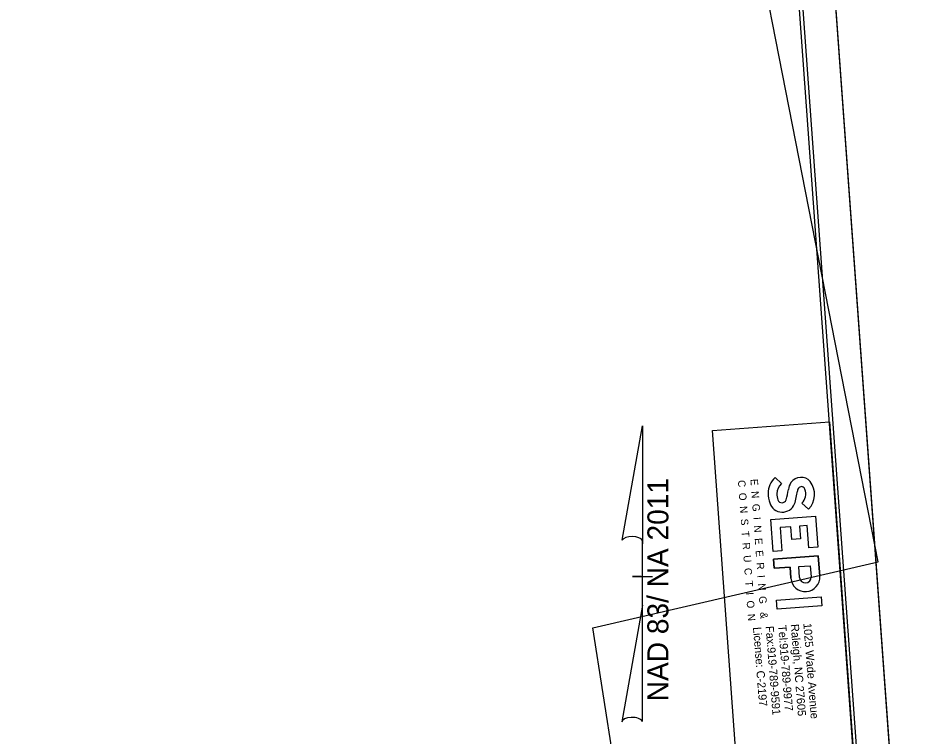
# Model space of a CAD drawing. Extents: x 2130580 to 2131806, y 642587 to 644485.
# Drawn here: x 2131193 to 2131806, y 643045 to 643536 of the extents above; entities that cross this region are included whole.
import ezdxf

# ---------------------------------------------------------------- set-up
doc = ezdxf.new("R2010")
doc.units = 0
for name, color, linetype in [('Old_Level_2', 7, 'Continuous'), ('Old_Level_58', 7, 'Continuous'), ('Old_Level_61', 7, 'Continuous'), ('Prop North Arrow NAD83 for Plan Sheets CELL', 7, 'Continuous'), ('Scratch_Level_1', 7, 'Continuous'), ('Sheet Border Standard 30in CELL', 7, 'Continuous'), ('Sheet Cutting Line CELL', 7, 'Continuous'), ('Sheet Plot Border Inside CELL', 7, 'Continuous'), ('Sheet Plot Border Outside CELL', 7, 'Continuous')]:
    doc.layers.add(name, color=color, linetype=linetype)

msp = doc.modelspace()

# ---------------------------------------------------------------- linework, layer by layer
at = {"layer": 'Old_Level_58'}
msp.add_lwpolyline([(2131747.69, 643259.81), (2131765.03, 643020.38), (2131685.21, 643014.6), (2131667.87, 643254.03)], close=True, dxfattribs=at)
at = {"layer": 'Old_Level_61'}
for p, q in [((2131710.59, 643221.85), (2131714.87, 643217.7)), ((2131733.51, 643200.1), (2131728.9, 643204.2)), ((2131707.6, 643193.22), (2131738.18, 643195.44)), ((2131738.18, 643195.44), (2131739.72, 643174.21)), ((2131709.19, 643171.3), (2131707.6, 643193.22)), ((2131721.42, 643188.1), (2131714, 643187.56)), ((2131714, 643187.56), (2131715.15, 643171.73)), ((2131722.06, 643179.35), (2131721.42, 643188.1)), ((2131732.64, 643188.91), (2131727.36, 643188.53)), ((2131727.36, 643188.53), (2131728, 643179.78)), ((2131733.74, 643173.78), (2131732.64, 643188.91)), ((2131728, 643179.78), (2131722.06, 643179.35)), ((2131715.15, 643171.73), (2131709.19, 643171.3)), ((2131739.72, 643174.21), (2131733.74, 643173.78)), ((2131741.16, 643154.37), (2131740.15, 643168.19)), ((2131727.35, 643153.37), (2131726.8, 643160.95)), ((2131711.62, 643137.91), (2131742.19, 643140.13)), ((2131742.19, 643140.13), (2131742.64, 643134.01)), ((2131712.06, 643131.79), (2131711.62, 643137.91)), ((2131742.64, 643134.01), (2131712.06, 643131.79))]:
    msp.add_line(p, q, dxfattribs=at)
for points in [[(2131721.39, 643152.94), (2131720.84, 643160.52), (2131710.03, 643159.73), (2131709.58, 643165.97), (2131740.15, 643168.19)], [(2131740.15, 643168.19), (2131709.58, 643165.97), (2131710.03, 643159.73), (2131720.84, 643160.52), (2131721.39, 643152.94)], [(2131740.15, 643168.19), (2131741.16, 643154.37)], [(2131726.8, 643160.95), (2131734.67, 643161.52), (2131735.22, 643153.94)], [(2131726.8, 643160.95), (2131734.67, 643161.52), (2131735.22, 643153.94)], [(2131727.35, 643153.37), (2131726.8, 643160.95)]]:
    msp.add_lwpolyline(points, dxfattribs=at)
for centre, radius, start, end in [((2131719.3, 643211.65), 13.42, 130.51252, 183.16622), ((2131731.99, 643211.89), 12.45, 148.17054, 171.49381), ((2131728.28, 643213.43), 8.51, 41.88007, 143.8084), ((2131722.9, 643210.25), 14.68, 316.27575, 37.12112), ((2131721.42, 643210.77), 9.54, 133.35739, 179.91595), ((2131682.34, 643218.18), 37.6, 341.9287, 353.20345), ((2131683.66, 643217.36), 42.47, 341.34779, 353.52913), ((2131730.65, 643211.82), 4.86, 138.97667, 170.99184), ((2131728.61, 643213.05), 2.54, 17.67407, 129.65781), ((2131722.2, 643210.72), 9.35, 315.76367, 19.34083), ((2131726.2, 643210.65), 20.3, 179.27694, 197.91753), ((2131723.72, 643210.36), 11.85, 177.9903, 199.19159), ((2131715.3, 643207.49), 2.95, 200.25648, 340.79139), ((2131715.51, 643207.21), 9.06, 198.04179, 337.7347), ((2131731.27, 643153.66), 9.91, 184.1516, 4.1516), ((2131731.27, 643153.66), 9.91, 184.1516, 4.1516), ((2131731.29, 643153.66), 3.95, 184.1516, 4.1516), ((2131731.29, 643153.66), 3.95, 184.1516, 4.1516)]:
    msp.add_arc(centre, radius, start, end, dxfattribs=at)
at = {"layer": 'Prop North Arrow NAD83 for Plan Sheets CELL'}
for p, q in [((2131605.9, 643178.92), (2131619.79, 643257.25)), ((2131619.88, 643257.25), (2131619.79, 643257.25)), ((2131619.88, 643257.25), (2131619.79, 643257.25)), ((2131619.88, 643257.25), (2131619.84, 643176.46)), ((2131619.82, 643134.55), (2131619.84, 643178.83)), ((2131619.84, 643176.46), (2131619.84, 643178.75)), ((2131613.07, 643154.16), (2131612.99, 643154.16)), ((2131619.07, 643154.16), (2131613.07, 643154.16)), ((2131613.16, 643154.16), (2131626.68, 643154.15)), ((2131619.82, 643134.55), (2131605.68, 643054.71)), ((2131619.88, 643055.04), (2131619.82, 643134.55))]:
    msp.add_line(p, q, dxfattribs=at)
for centre, start_param, end_param in [((2131612.89, 643178.08), 0.216388, 2.908219), ((2131612.84, 643054.42), 0.201328, 3.141593)]:
    msp.add_ellipse(centre, major_axis=(7.15, -0.05), ratio=0.461098, start_param=start_param, end_param=end_param, dxfattribs=at)
at = {"layer": 'Scratch_Level_1'}
msp.add_lwpolyline([(2131551.07, 644337.91), (2130579.8, 644180.68), (2130824.52, 642834.57), (2131607.08, 642983.58), (2131586.04, 643119.01), (2131781.17, 643164.17)], close=True, dxfattribs=at)
at = {"layer": 'Sheet Border Standard 30in CELL'}
msp.add_lwpolyline([(2131779.49, 642820.85), (2131671.12, 644316.93), (2130623.86, 644241.07), (2130732.23, 642744.99)], close=True, dxfattribs=at)
at = {"layer": 'Sheet Cutting Line CELL'}
msp.add_line((2131805.65, 642805.7), (2131683.99, 644485.3), dxfattribs=at)
at = {"layer": 'Sheet Plot Border Inside CELL'}
msp.add_lwpolyline([(2131782.93, 642808.57), (2131662.53, 644470.71), (2130610.19, 644394.49), (2130730.59, 642732.34)], close=True, dxfattribs=at)
at = {"layer": 'Sheet Plot Border Outside CELL'}
msp.add_lwpolyline([(2131805.65, 642805.7), (2131683.99, 644485.3), (2130586.86, 644405.83), (2130708.52, 642726.23)], close=True, dxfattribs=at)

# ---------------------------------------------------------------- texts
at = {"layer": 'Old_Level_2'}
for s, height, rotation, p in [('C  O  N  S  T  R  U  C  T  I  O  N', 5.1, 274.15161, (2131685.14, 643219.89)), ('E  N  G  I  N  E  E  R  I  N  G   &', 5.1, 274.15161, (2131693.71, 643220.68)), ('Fax:919-789-9591', 5.5891, 274.49105, (2131704.06, 643120.06)), ('Tel:919-789-9977 ', 5.5891, 274.49105, (2131712.67, 643120.73)), ('Raleigh, NC 27605', 5.5891, 274.49105, (2131721.28, 643121.41)), ('1025 Wade Avenue', 5.5891, 274.49105, (2131729.89, 643122.08)), ('License: C-2197', 5.5891, 274.49105, (2131695.45, 643119.38))]:
    msp.add_text(s, height=height, rotation=rotation, dxfattribs=at).set_placement(p)
at = {"layer": 'Prop North Arrow NAD83 for Plan Sheets CELL'}
msp.add_text('NAD 83/ NA 2011', height=14.365, rotation=89.97607, dxfattribs=at).set_placement((2131637.58, 643068.8))

doc.saveas('drawing.dxf')
